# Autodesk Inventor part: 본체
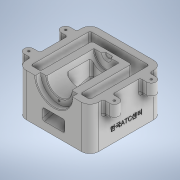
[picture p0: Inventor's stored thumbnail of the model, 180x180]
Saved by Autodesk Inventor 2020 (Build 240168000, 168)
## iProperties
Created: 2022-03
Part Number: 본체
Material: 일반
Document SubType Name: Modeling
Designer: Administrator
Density: 1 g/cm^3
Appearance: 기본값
Author: Administrator
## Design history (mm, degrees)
sketch "스케치1"
  geometry: L1 (-55, 55)-(55, 55); L2 (55, 55)-(55, -55); L3 (55, -55)-(-55, -55); L4 (-55, -55)-(-55, 55); L5 (-55, 55)-(55, -55); L6 (55, 55)-(-55, -55); L7 (45, 45)-(-45, 45); L8 (-45, 45)-(-45, -45); L9 (-45, -45)-(45, -45); L10 (45, -45)-(45, 45); 1 further point
  constraints: 20 end point, 4 parallel, 2 midpoint, 2 perpendicular, 1 horizontal, 3 other
  dimensions: "d0" = 110 distance of L1.start L1.end; "d1" = 110 distance of L3.end L1.start; "d2" = 10 distance between parallel lines of L1 L7
extrude "돌출1" new body sketch "스케치1" distance "d3" = 65; taper "d4" = 0 deg
sketch "스케치2"
  geometry: L1 (-65, 28)-(65, 28); L2 (55, 55)-(-55, 55) reference; L3 (-65, -28)-(65, -28); L4 (-65, 35)-(-53.105, 35); L5 (-65, 21)-(-53.105, 21); L6 (-53.105, 21)-(-53.105, 35); L7 (-65, -21)-(-51.736, -21); L8 (-51.736, -21)-(-51.736, -35); L9 (-51.736, -35)-(-65, -35); L10 (65, 35)-(51.257, 35); L11 (65, 21)-(51.91, 21); L12 (51.91, 21)-(51.257, 35); L13 (65, -35)-(52.819, -35); L14 (65, -21)-(51.257, -21); L15 (51.257, -21)-(52.819, -35); A1 r 7 centre (-65, 28) between (-65, 35) and (-65, 21); A2 r 7 centre (65, 28) between (65, 21) and (65, 35); A3 r 7 centre (-65, -28) between (-65, -21) and (-65, -35); A4 r 7 centre (65, -28) between (65, -35) and (65, -21); 5 further points
  constraints: 28 end point, 9 horizontal, 8 point on circle, 4 centre point, 4 midpoint, 4 tangent, 4 vertical alignment, 2 perpendicular, 1 horizontal alignment, 1 vertical
  dimensions: "d5" = 14 diameter of A1; "d6" = 14 diameter of A2; "d7" = 130 distance of L1.end L1.start; "d8" = 14 diameter of A4; "d9" = 14 diameter of A3; "d10" = 130 distance of L3.end L3.start; "d12" = 27 distance from line of L1.start L2; "d13" = 56 distance of L3.start L1.start
extrude "돌출2" join sketch "스케치2" distance "d14" = 20; taper "d15" = 0 deg
sketch "스케치3"
  geometry: L1 (0, 65)-(110, 65) reference; L2 (0, 0)-(110, 0) reference; A1 r 30 centre (55, 65) between (25, 65) and (85, 65); 3 further points
  constraints: 2 midpoint, 2 point on circle, 2 point on line, 1 centre point, 1 coincident, 1 vertical alignment
  dimensions: "d16" = 60 diameter of A1
extrude "돌출3" join sketch "스케치3" distance "d17" = 88; taper "d18" = 0 deg
sketch "스케치4"
  geometry: L1 (0, 0)-(110, 0) reference; L2 (0, 65)-(110, 65) reference; A1 r 19 centre (55, 65) between (36, 65) and (74, 65); 2 further points
  constraints: 2 midpoint, 2 point on circle, 2 point on line, 1 centre point, 1 vertical alignment
  dimensions: "d19" = 38 diameter of A1
extrude "돌출4" cut sketch "스케치4" distance "d20" = 80; taper "d21" = 0 deg
sketch "스케치5"
  geometry: L1 (0, 0)-(110, 0) reference; L2 (36, 65)-(74, 65) reference; C1 r 28 at (55, 65); A1 r 19 centre (55, 65) between (36, 65) and (74, 65) reference; 2 further points
  constraints: 1 centre point, 1 coincident, 1 midpoint, 1 vertical alignment
  dimensions: "d22" = 56 diameter of C1
extrude "돌출5" cut sketch "스케치5" distance "d23" = 8; taper "d24" = 0 deg
sketch "스케치6"
  geometry: L1 (-19, 25)-(19, 25) reference; L2 (-7.5, 25)-(-5.191, 29); L3 (-5.191, 29)-(0, 29); L4 (0, 0)-(0, 43.388); 1 further point
  constraints: 6 end point, 2 point on line, 1 horizontal, 1 vertical
  dimensions: "d25" = 15 diameter of L2.start L4; "d27" = 30 deg angle of L4 L2; "d28" = 4 distance between parallel lines of L1 L3
revolve "회전1" sketch "스케치6" stored, may be unused: angle "d29" = 90 deg
fillet "모깎기1" dims "d30" = 1
node "스케치7"
chamfer "모따기1" distance "d31" = 1; stored, may be unused: second distance "d32" = 2, angle "d33" = 45 deg
sketch "스케치9"
  geometry: L1 (33, 35)-(33, 65) reference; L2 (-45, 0)-(-45, 65) reference; L3 (33, 30)-(-45, 9.1); L4 (-45, 35)-(33, 35) reference; L5 (33, 30)-(33, 44.666); L6 (33, 44.666)-(-45, 44.666); L7 (-45, 65)-(-45, 35) reference; 1 further point
  constraints: 6 end point, 5 point on line, 1 perpendicular
  dimensions: "d34" = 5 distance of L1.start L3.start
extrude "돌출6" join sketch "스케치9" stored distance "d36" = 60; taper "d37" = 0 deg
sketch "스케치10"
  geometry: L1 (0, 0)-(0, 78) reference; L2 (0, 0)-(0, 78) reference; L3 (7.942, 0)-(0, 0) reference; L4 (7.942, 78)-(7.942, 0) reference; L5 (7.942, 78)-(0, 78) reference; L6 (0, 0)-(7.942, 0) reference; L7 (0, 78)-(0, 0); L8 (7.942, 0)-(0, 0) reference; L9 (0, 0)-(7.942, 0); L10 (7.942, 78)-(7.942, 0) reference; L11 (7.942, 0)-(7.942, 78); L12 (7.942, 78)-(0, 78); 3 further points
  constraints: 8 end point, 3 perpendicular, 1 collinear
extrude "돌출7" join sketch "스케치10" stored distance "d38" = 60; taper "d39" = 0 deg; dims "d5" = 14, "d6" = 14, "d7" = 130, "d8" = 14, "d9" = 14, "d10" = 130, "d12" = 27, "d13" = 56
sketch "스케치11"
  geometry: L1 (7.942, 0)-(7.942, -78) reference; L2 (7.942, 0)-(0, 0) reference; L3 (0, -78)-(0, 0) reference; L4 (7.942, -78)-(0, -78) reference; 1 further point
extrude "돌출8" join sketch "스케치11" stored distance "d40" = 60; taper "d41" = 0 deg
sketch "스케치12"
  geometry: L1 (-45, 9.1)-(33, 30) reference; L2 (-55, 11.597)-(19, 31.425); L3 (-55, 0)-(-55, 65) reference; L4 (-46, 46)-(24, 46) reference; L5 (19, 31.425)-(19, 57.378); L6 (19, 57.378)-(-19, 57.378); L7 (-19, 57.378)-(-19, 38.843); L8 (-19, 34.622)-(19, 57.378); L9 (19, 34.622)-(-19, 57.378); L10 (-47, 65)-(-47, 45) reference; L11 (-55, 29.197)-(-19, 38.843); 3 further points
  constraints: 14 end point, 4 point on line, 3 midpoint, 3 parallel
  dimensions: "d42" = 5 distance between parallel lines of L1 L2; "d44" = 38 distance of L5.end L6.end; "d46" = 36 distance between parallel lines of L3 L7; "d47" = 17 distance between parallel lines of L2 L11
extrude "돌출9" cut sketch "스케치12" stored distance "d48" = 34; taper "d49" = 0 deg
fillet "모깎기2" dims "d50" = 13
fillet "모깎기3" dims "d51" = 3
fillet "모깎기4" dims "d52" = 3
fillet "모깎기5" dims "d53" = 3
fillet "모깎기6" dims "d54" = 3
fillet "모깎기7" dims "d55" = 3
fillet "모깎기8" dims "d56" = 3
fillet "모깎기9" dims "d57" = 3
fillet "모깎기10" dims "d58" = 2.9
fillet "모깎기11" dims "d59" = 3
sketch "스케치13" dims "d60" = 46
  geometry: L1 (28, 65)-(82, 65) reference; 3 further points
  constraints: 2 vertical alignment, 1 midpoint, 2 other
hole "구멍1" sketch "스케치13" at (55, 42) diameter "d61" = 3.242; stored, may be unused: countersink angle "d65" = 60 deg, drill point angle "d67" = 118 deg; dims "d62" = 9, "d63" = 4.25, "d64" = 2, "d66" = 11
sketch "스케치14"
  geometry: A1 r 7 centre (-65, 28) between (-65, 35) and (-65, 21) reference; A2 r 7 centre (-65, -28) between (-65, -21) and (-65, -35) reference; A3 r 7 centre (65, 28) between (65, 21) and (65, 35) reference; A4 r 7 centre (65, -28) between (65, -35) and (65, -21) reference; A5 r 4 centre (65, -28) between (65, -32) and (65, -24) reference; 5 further points
  constraints: 4 coincident
hole "구멍2" sketch "스케치14" at (65, 28), (65, -28), (-65, -28), (-65, 28) diameter "d68" = 3.242; stored, may be unused: countersink angle "d72" = 60 deg, drill point angle "d74" = 118 deg; dims "d69" = 9, "d70" = 4.25, "d71" = 2, "d73" = 11
sketch "스케치15"
  geometry: L1 (-65, -13)-(0, -13) reference; 2 further points
  constraints: 1 other
  dimensions: "d75" = 55 distance from line of L1 point (-20, 42); "d76" = 20 distance of point (0, 42) point (-20, 42)
feature "엠보싱1" sketch "스케치15" dims "d0" = 110, "d1" = 110, "d2" = 10, "d5" = 14, "d6" = 14, "d7" = 130, "d8" = 14, "d9" = 14, "d10" = 130, "d12" = 27, "d13" = 56, "d77" = 0.5, "d78" = 0
node "솔리드1"
node "투영된 루프1"
node "투영된 루프2"
feature "A9D066F2-1C7D-4E18-AEED-F7BC21143FA4" dims "d68" = 3.242, "d69" = 9, "d70" = 4.25, "d71" = 2, "d72" = 60 deg, "d73" = 11, "d74" = 118 deg
other parameters: "d43" = 17
